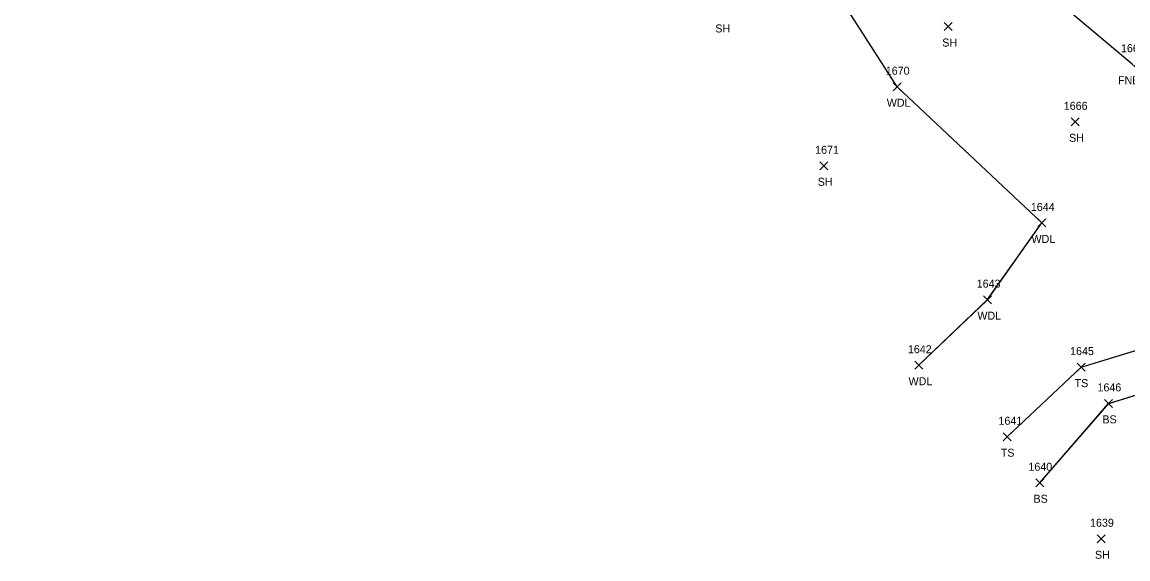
# Model space of a CAD drawing. Extents: x 1415642 to 1422021, y 544543 to 547232.
# Drawn here: x 1415689.9 to 1415966.4, y 546785.9 to 546920.1 of the extents above; entities that cross this region are included whole.
import ezdxf

# ---------------------------------------------------------------- set-up
doc = ezdxf.new("R2010")
doc.units = 0
for name, color, linetype in [('L_A', 7, 'Continuous'), ('L_I', 7, 'Continuous'), ('L_TIC', 7, 'Continuous'), ('LAWA', 7, 'Continuous'), ('LELB', 7, 'Continuous'), ('LFNC', 7, 'Continuous')]:
    doc.layers.add(name, color=color, linetype=linetype)

msp = doc.modelspace()

# ---------------------------------------------------------------- linework, layer by layer
at = {"layer": 'L_TIC'}
for points in [[(1415920.46, 546918.03), (1415922.46, 546920.03)], [(1415922.46, 546918.03), (1415920.46, 546920.03)], [(1415907.68, 546902.98), (1415909.68, 546904.98)], [(1415909.68, 546902.98), (1415907.68, 546904.98)], [(1415952.18, 546894.21), (1415954.18, 546896.21)], [(1415954.18, 546894.21), (1415952.18, 546896.21)], [(1415889.35, 546883.21), (1415891.35, 546885.21)], [(1415891.35, 546883.21), (1415889.35, 546885.21)], [(1415943.85, 546868.92), (1415945.85, 546870.92)], [(1415945.85, 546868.92), (1415943.85, 546870.92)], [(1415930.31, 546849.74), (1415932.31, 546851.74)], [(1415932.31, 546849.74), (1415930.31, 546851.74)], [(1415913.11, 546833.35), (1415915.11, 546835.35)], [(1415915.11, 546833.35), (1415913.11, 546835.35)], [(1415953.66, 546832.88), (1415955.66, 546834.88)], [(1415955.66, 546832.88), (1415953.66, 546834.88)], [(1415960.56, 546823.81), (1415962.56, 546825.81)], [(1415962.56, 546823.81), (1415960.56, 546825.81)], [(1415935.18, 546815.47), (1415937.18, 546817.47)], [(1415937.18, 546815.47), (1415935.18, 546817.47)], [(1415943.33, 546803.96), (1415945.33, 546805.96)], [(1415945.33, 546803.96), (1415943.33, 546805.96)], [(1415958.65, 546789.96), (1415960.65, 546791.96)], [(1415960.65, 546789.96), (1415958.65, 546791.96)]]:
    msp.add_lwpolyline(points, dxfattribs=at)
at = {"layer": 'LAWA'}
for points in [[(1415914.11, 546834.35), (1415931.31, 546850.74), (1415944.85, 546869.92), (1415908.68, 546903.98), (1415882.09, 546945.44), (1415862.73, 546979.72), (1415851.29, 546999.16), (1415831.18, 547012.42), (1415802.21, 547036.19), (1415763.17, 547054.94), (1415718.14, 547089.46), (1415689.93, 547108.01)], [(1415914.12, 546834.35), (1415931.31, 546850.75), (1415944.86, 546869.92), (1415908.68, 546903.98), (1415882.1, 546945.44), (1415862.73, 546979.72), (1415851.29, 546999.15), (1415831.18, 547012.42), (1415802.2, 547036.19), (1415763.17, 547054.94), (1415718.15, 547089.45), (1415689.93, 547108.01)]]:
    msp.add_lwpolyline(points, dxfattribs=at)
at = {"layer": 'LELB'}
for points in [[(1415936.18, 546816.47), (1415954.66, 546833.88), (1415975.39, 546840.17), (1415996.48, 546829.17), (1416009.09, 546812.92), (1416027.82, 546816.84), (1416044.33, 546828.1), (1416051.15, 546839.14)], [(1415936.19, 546816.47), (1415954.66, 546833.88), (1415975.4, 546840.17), (1415996.49, 546829.17), (1416009.1, 546812.92), (1416027.83, 546816.84), (1416044.34, 546828.1), (1416051.16, 546839.14)], [(1415944.33, 546804.96), (1415961.56, 546824.81), (1415976.83, 546829.5), (1415993.3, 546822.66), (1416007.51, 546807.48), (1416035.92, 546807.45), (1416051.3, 546817.96), (1416069.09, 546824.45)], [(1415944.33, 546804.96), (1415961.57, 546824.81), (1415976.84, 546829.5), (1415993.31, 546822.66), (1416007.52, 546807.48), (1416035.92, 546807.45), (1416051.3, 546817.96), (1416069.1, 546824.45)]]:
    msp.add_lwpolyline(points, dxfattribs=at)
at = {"layer": 'LFNC'}
for points in [[(1416115.75, 546796.75), (1416105.56, 546801.9), (1416090.13, 546811.78), (1416082.81, 546817.76), (1416078.29, 546817.48), (1416069.09, 546824.45), (1416051.15, 546839.14), (1416026.27, 546859.13), (1416002.28, 546878.71), (1415967.43, 546909.62), (1415937.82, 546934.52), (1415909.35, 546961.09), (1415874.55, 546995.04)], [(1416115.75, 546796.75), (1416105.57, 546801.9), (1416090.14, 546811.78), (1416082.82, 546817.76), (1416078.29, 546817.48), (1416069.1, 546824.45), (1416051.16, 546839.14), (1416026.28, 546859.13), (1416002.28, 546878.71), (1415967.43, 546909.62), (1415937.83, 546934.51), (1415909.36, 546961.09), (1415874.56, 546995.04)]]:
    msp.add_lwpolyline(points, dxfattribs=at)

# ---------------------------------------------------------------- texts
at = {"layer": 'L_A'}
for s, p in [('SH', (1415863.21, 546917.55)), ('SH', (1415919.95, 546914.03)), ('FNBW', (1415963.9, 546904.62)), ('WDL', (1415906.09, 546898.98)), ('SH', (1415951.67, 546890.21)), ('SH', (1415888.84, 546879.21)), ('WDL', (1415942.27, 546864.92)), ('WDL', (1415928.73, 546845.74)), ('WDL', (1415911.53, 546829.35)), ('TS', (1415953.06, 546828.88)), ('BS', (1415960, 546819.81)), ('TS', (1415934.59, 546811.47)), ('BS', (1415942.77, 546799.96)), ('SH', (1415958.14, 546785.96))]:
    msp.add_text(s, height=2, dxfattribs=at).set_placement(p)
at = {"layer": 'L_I'}
for s, p in [('1667', (1415964.64, 546912.62)), ('1670', (1415905.85, 546906.98)), ('1666', (1415950.34, 546898.21)), ('1671', (1415888.18, 546887.21)), ('1644', (1415942.11, 546872.92)), ('1643', (1415928.57, 546853.74)), ('1642', (1415911.37, 546837.35)), ('1645', (1415951.92, 546836.88)), ('1646', (1415958.77, 546827.81)), ('1641', (1415934.01, 546819.47)), ('1640', (1415941.5, 546807.96)), ('1639', (1415956.9, 546793.96))]:
    msp.add_text(s, height=2, dxfattribs=at).set_placement(p)

doc.saveas('drawing.dxf')
